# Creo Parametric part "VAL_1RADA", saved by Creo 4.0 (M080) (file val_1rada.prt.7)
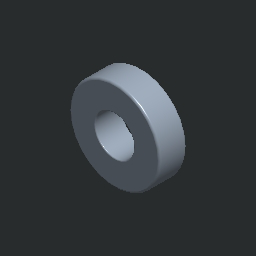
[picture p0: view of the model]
Units: Custom; MM, KILOGRAM, SECS
Materials in the file: OCEL_N

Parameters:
  MFG_WP_MATERIAL = "RO6"
  NAZOV = "VAL_1RADA"
  PTC_MATERIAL_NAME = "OCEL_N"

Other parameters: HMOTNOST, HUSTOTA

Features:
  1. round
  2. round

Named dimensions: velke_D

Layers: 1, 2, 3, 4, 5, 6, 7, 8, 9, 10, 11, 12, 13, 14, 15, 16, 17, 18, 19, 20, 21, 22, 23, 24, 25, 26, 27, 28, 29, 30, 31, 32

Family table entries: GENERIC, LOZISKO_NU203, VAL_1RADA, value(d_val), 2/D, 2/(, value(i_val), LOZISKO_NU204, VAL_1RADA, !/4, 2/,, LOZISKO_NU2204, VAL_1RADA, !/4, 2/2, LOZISKO_NU304, VAL_1RADA, !/4, 2/J, 2/., LOZISKO_NU205, VAL_1RADA, !/9, 2/J, 2/., LOZISKO_NU2205, VAL_1RADA, !/9, 2/J, 2/2, LOZISKO_NU305, VAL_1RADA, !/9, 2/O, 2/1, LOZISKO_NU2305, VAL_1RADA, !/9, 2/O, 2/8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

Surfaces: 8 torus, 2 plane, 2 cylinder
